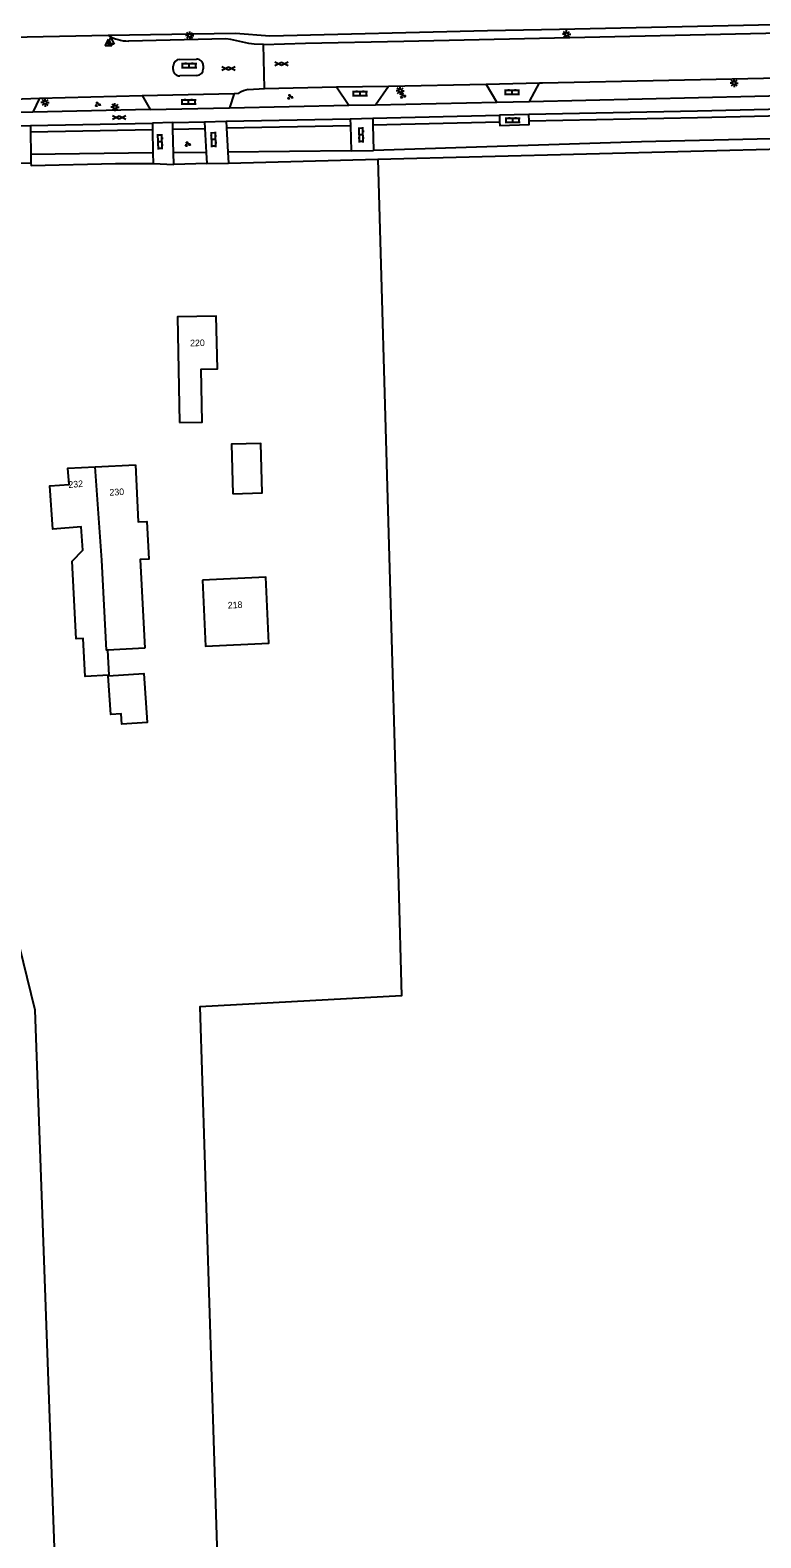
# Model space of a CAD drawing. Extents: x 128999 to 131010, y 395498 to 399007.
# Drawn here: x 130522.1 to 130633, y 395907.2 to 396136.1 of the extents above; entities that cross this region are included whole.
import ezdxf

# ---------------------------------------------------------------- set-up
doc = ezdxf.new("R2010")
doc.units = 0
for name, color, linetype in [('gg-afsc-hekwerk', 7, 'Continuous'), ('gg-anno-huisnummerreeks BGT', 7, 'Continuous'), ('gg-bbg-bijgebouw', 7, 'Continuous'), ('gg-bbg-gedigitaliseerde bebouwing', 7, 'Continuous'), ('gg-bbg-gedigitaliseerde bijgebouw', 7, 'Continuous'), ('gg-bbg-hoofdgebouw', 7, 'Continuous'), ('gg-bbg-tussenscheiding', 7, 'Continuous'), ('gg-knt-verharding', 7, 'Continuous'), ('gt-grn-groengrens', 7, 'Continuous'), ('gt-grn-groengrens NZ', 7, 'Continuous'), ('gt-grn-weggrens', 7, 'Continuous'), ('gt-symb-gesloten verharding', 7, 'Continuous'), ('gt-symb-groenvak', 7, 'Continuous'), ('gt-symb-klinker verharding', 7, 'Continuous'), ('gt-symb-lichtmast', 7, 'Continuous'), ('gt-symb-waterafsluiter', 7, 'Continuous')]:
    doc.layers.add(name, color=color, linetype=linetype)

# ---------------------------------------------------------------- blocks, each defined once
blk = doc.blocks.new('gt0-KL1')
at = {"layer": 'gt-symb-klinker verharding'}
for p, q in [((-1.15, 0.3), (1.15, 0.3)), ((-1, -0.3), (-1, 0.3)), ((-0.5, 0.3), (-0.5, 0.45)), ((0, -0.3), (0, 0.3)), ((0.5, 0.3), (0.5, 0.45)), ((1, -0.3), (1, 0.3)), ((-1.15, -0.3), (1.15, -0.3)), ((-0.5, -0.45), (-0.5, -0.3)), ((0.5, -0.45), (0.5, -0.3))]:
    blk.add_line(p, q, dxfattribs=at)
blk = doc.blocks.new('gt0-GESVH1')
at = {"layer": 'gt-symb-gesloten verharding'}
for p, q in [((-0.99, -0.26), (0.01, 0.24)), ((0.01, -0.26), (-0.99, 0.24)), ((0.01, 0.24), (1.01, -0.26)), ((1.01, 0.24), (0.01, -0.26))]:
    blk.add_line(p, q, dxfattribs=at)
blk = doc.blocks.new('gt0-LMAST')
at = {"layer": 'gt-symb-lichtmast'}
for p, q in [((-0.18, 0.17), (-0.45, 0.44)), ((-0.01, 0.25), (-0.01, 0.62)), ((0.17, 0.17), (0.44, 0.44)), ((-0.26, 0), (-0.63, 0)), ((-0.18, -0.18), (-0.45, -0.45)), ((-0.01, -0.25), (-0.01, -0.63)), ((0.44, -0.45), (0.17, -0.18)), ((0.24, 0), (0.62, 0))]:
    blk.add_line(p, q, dxfattribs=at)
blk.add_circle((-0.01, 0), 0.25, dxfattribs=at)
blk = doc.blocks.new('gt0-GRVAK')
at = {"layer": 'gt-symb-groenvak'}
for p, q in [((-0.11, 0.19), (-0.23, 0.24)), ((-0.18, 0.15), (0.09, 0.15)), ((-0.09, 0.21), (-0.16, 0.32)), ((-0.05, 0.21), (-0.05, 0.39)), ((0, 0.21), (0.06, 0.32)), ((0.01, 0.19), (0.13, 0.24)), ((0.26, -0.05), (0.2, 0.06)), ((0.31, -0.05), (0.31, 0.13)), ((0.35, -0.05), (0.41, 0.06)), ((-0.24, -0.23), (-0.36, -0.18)), ((-0.32, -0.26), (-0.05, -0.26)), ((-0.23, -0.21), (-0.29, -0.1)), ((-0.18, -0.2), (-0.18, -0.02)), ((-0.14, -0.21), (-0.07, -0.1)), ((-0.12, -0.23), (0, -0.18)), ((0.24, -0.07), (0.12, -0.02)), ((0.17, -0.11), (0.44, -0.11)), ((0.37, -0.07), (0.49, -0.02))]:
    blk.add_line(p, q, dxfattribs=at)
blk = doc.blocks.new('gt0-WAFSL')
at = {"layer": 'gt-symb-waterafsluiter'}
for p, q in [((-0.5, -0.33), (0, 0.67)), ((0, 0.67), (0.5, -0.33)), ((0.5, -0.33), (-0.5, -0.33))]:
    blk.add_line(p, q, dxfattribs=at)

msp = doc.modelspace()

# ---------------------------------------------------------------- linework, layer by layer
at = {"layer": 'gg-afsc-hekwerk'}
msp.add_line((130548.91, 396115.83), (130543.9, 396115.68), dxfattribs=at)
at = {"layer": 'gg-bbg-bijgebouw'}
msp.add_lwpolyline([(130552.84, 396065.7), (130557.31, 396065.82), (130557.11, 396073.33), (130552.64, 396073.21), (130552.84, 396065.7)], dxfattribs=at)
at = {"layer": 'gg-bbg-gedigitaliseerde bebouwing'}
msp.add_lwpolyline([(130548.26, 396052.59), (130548.73, 396042.58), (130558.34, 396043.04), (130557.86, 396053.05), (130548.26, 396052.59)], dxfattribs=at)
at = {"layer": 'gg-bbg-gedigitaliseerde bijgebouw'}
msp.add_lwpolyline([(130533.93, 396038.04), (130539.33, 396038.42), (130539.84, 396030.97), (130536.03, 396030.7), (130535.92, 396032.29), (130534.34, 396032.18), (130533.93, 396038.04)], dxfattribs=at)
at = {"layer": 'gg-bbg-hoofdgebouw'}
for p, q in [((130531.99, 396069.8), (130538.07, 396070.12)), ((130539.52, 396042.28), (130533.83, 396041.98))]:
    msp.add_line(p, q, dxfattribs=at)
for points in [[(130544.77, 396076.51), (130548.19, 396076.58), (130548.04, 396084.62), (130550.51, 396084.67), (130550.35, 396092.67), (130544.46, 396092.56), (130544.77, 396076.51)], [(130533.83, 396041.98), (130534.03, 396038.14), (130530.44, 396037.95), (130530.13, 396043.75), (130529.11, 396043.7), (130528.5, 396055.47), (130530.11, 396057.13), (130529.84, 396060.67), (130525.56, 396060.35), (130525.07, 396066.89), (130528.01, 396067.11), (130527.83, 396069.58), (130531.99, 396069.8)], [(130538.07, 396070.12), (130538.52, 396061.44), (130539.83, 396061.51), (130540.13, 396055.77), (130538.82, 396055.7), (130539.52, 396042.28)]]:
    msp.add_lwpolyline(points, dxfattribs=at)
at = {"layer": 'gg-bbg-tussenscheiding'}
msp.add_lwpolyline([(130533.83, 396041.98), (130533.67, 396041.97), (130532.97, 396055.64), (130531.99, 396069.8)], dxfattribs=at)
at = {"layer": 'gg-knt-verharding'}
for p, q in [((130533.95, 396135.3), (130519.18, 396134.98)), ((130557.5, 396133.91), (130556.11, 396133.95)), ((130557.68, 396127.24), (130557.5, 396133.91)), ((130543.81, 396130.13), (130543.82, 396130.63)), ((130544.78, 396131.66), (130547.36, 396131.7)), ((130548.37, 396130.72), (130548.38, 396130.21)), ((130547.4, 396129.21), (130544.83, 396129.15)), ((130576.5, 396127.61), (130591.3, 396127.88)), ((130591.3, 396127.88), (130591.32, 396127.88)), ((130591.32, 396127.88), (130599.37, 396128.07)), ((130592.92, 396125.16), (130591.32, 396127.88)), ((130597.85, 396125.27), (130599.37, 396128.07)), ((130599.37, 396128.07), (130599.84, 396128.08)), ((130599.84, 396128.08), (130688.07, 396129.97)), ((130516.59, 396125.52), (130523.51, 396125.75)), ((130523.51, 396125.75), (130522.52, 396123.64)), ((130523.51, 396125.75), (130539.08, 396126.16)), ((130539.08, 396126.16), (130553.04, 396126.48)), ((130539.08, 396126.16), (130540.31, 396124.02)), ((130553.04, 396126.48), (130552.35, 396124.3)), ((130553.04, 396126.48), (130553.79, 396126.53)), ((130555.18, 396127.07), (130557.68, 396127.24)), ((130557.68, 396127.24), (130568.6, 396127.47)), ((130568.6, 396127.47), (130576.5, 396127.61)), ((130568.6, 396127.47), (130570.48, 396124.68)), ((130574.49, 396124.75), (130576.5, 396127.61)), ((130522.52, 396123.64), (130518.15, 396123.54)), ((130540.31, 396124.02), (130522.52, 396123.64)), ((130540.31, 396124.02), (130552.35, 396124.3)), ((130552.35, 396124.3), (130570.48, 396124.68)), ((130570.48, 396124.68), (130574.49, 396124.75)), ((130574.49, 396124.75), (130592.92, 396125.16)), ((130592.92, 396125.16), (130597.85, 396125.27)), ((130597.79, 396123.27), (130593.3, 396123.16)), ((130597.82, 396122.27), (130597.79, 396123.27)), ((130518.59, 396121.55), (130522.14, 396121.63)), ((130522.14, 396121.63), (130540.66, 396121.99)), ((130522.14, 396121.63), (130522.15, 396120.63)), ((130543.75, 396122.05), (130540.66, 396121.99)), ((130540.66, 396121.99), (130540.68, 396120.99)), ((130540.68, 396120.99), (130540.74, 396117.44)), ((130543.75, 396122.05), (130548.54, 396122.18)), ((130543.77, 396121.05), (130543.75, 396122.05)), ((130543.77, 396121.05), (130548.6, 396121.18)), ((130543.86, 396117.47), (130543.77, 396121.05)), ((130548.54, 396122.18), (130551.87, 396122.27)), ((130548.54, 396122.18), (130548.6, 396121.18)), ((130548.6, 396121.18), (130548.81, 396117.53)), ((130551.87, 396122.27), (130570.68, 396122.63)), ((130551.87, 396122.27), (130551.92, 396121.27)), ((130551.92, 396121.27), (130552.12, 396117.57)), ((130570.68, 396122.63), (130574.09, 396122.73)), ((130570.68, 396122.63), (130570.71, 396121.63)), ((130570.71, 396121.63), (130570.81, 396117.75)), ((130574.09, 396122.73), (130593.3, 396123.16)), ((130574.09, 396122.73), (130574.11, 396121.73)), ((130574.11, 396121.73), (130574.22, 396117.8)), ((130593.3, 396123.16), (130593.33, 396122.16)), ((130522.15, 396120.63), (130522.21, 396117.23)), ((130522.21, 396117.23), (130522.23, 396115.88)), ((130540.74, 396117.44), (130540.77, 396115.86)), ((130543.9, 396115.68), (130543.86, 396117.47)), ((130548.81, 396117.53), (130548.91, 396115.83)), ((130552.12, 396117.57), (130552.21, 396115.89)), ((130522.23, 396115.88), (130518.96, 396115.78))]:
    msp.add_line(p, q, dxfattribs=at)
for points in [[(130779.08, 396140.06), (130602.43, 396136.21), (130591.5, 396136)], [(130557.5, 396133.91), (130563.91, 396134.13), (130578.82, 396134.43), (130777.82, 396138.84)], [(130591.5, 396136), (130558.49, 396135.2), (130553.25, 396135.59), (130533.95, 396135.3)], [(130556.11, 396133.95), (130555.3, 396134.04), (130552.57, 396134.65), (130551.81, 396134.77), (130537.05, 396134.43)], [(130597.85, 396125.27), (130649.18, 396126.45), (130656.22, 396126.63), (130663.5, 396127.01), (130670.92, 396127.54), (130682.3, 396128.28), (130686.74, 396128.49), (130690.65, 396128.56)], [(130691.26, 396126.57), (130686.91, 396126.43), (130682.58, 396126.23), (130671.33, 396125.5), (130663.58, 396124.95), (130656.49, 396124.59), (130649.22, 396124.39), (130623.35, 396123.79), (130597.79, 396123.27)], [(130593.33, 396122.16), (130593.35, 396121.62), (130597.83, 396121.75), (130597.82, 396122.27)]]:
    msp.add_lwpolyline(points, dxfattribs=at)
for centre, radius, start, end in [((130537.01, 396140.27), 5.83, 238.3369, 270.4457), ((130544.83, 396130.65), 1.01, 92.5004, 180.7794), ((130544.79, 396130.12), 0.979, 179.4419, 272.328), ((130547.38, 396130.71), 0.994, 0.6008, 91.1214), ((130547.38, 396130.21), 0.997, 271.0386, 0.0627), ((130555.89, 396123.17), 3.97, 100.2679, 121.9669)]:
    msp.add_arc(centre, radius, start, end, dxfattribs=at)
at = {"layer": 'gt-grn-groengrens'}
for p, q in [((130574.84, 396116.49), (130690.6, 396119.51)), ((130540.74, 396117.44), (130522.21, 396117.23)), ((130548.81, 396117.53), (130543.86, 396117.47)), ((130570.81, 396117.75), (130552.12, 396117.57)), ((130552.21, 396115.89), (130574.84, 396116.49))]:
    msp.add_line(p, q, dxfattribs=at)
for points in [[(130691.72, 396120.93), (130656.6, 396120.09), (130614.87, 396119.12), (130574.22, 396117.8)], [(130574.84, 396116.49), (130577.98, 396006.36), (130578.46, 395989.5), (130547.84, 395987.81), (130552.09, 395852.97), (130527.73, 395852.24), (130522.86, 395987.31), (130519.88, 395999.52), (130514.76, 396007.01), (130516.32, 396021.25), (130497.85, 396023.27)], [(130522.23, 396115.88), (130522.24, 396115.54), (130535.06, 396115.84), (130540.77, 396115.86)]]:
    msp.add_lwpolyline(points, dxfattribs=at)
at = {"layer": 'gt-grn-groengrens NZ'}
for p, q in [((130522.15, 396120.63), (130540.68, 396120.99)), ((130551.92, 396121.27), (130570.71, 396121.63)), ((130574.11, 396121.73), (130593.33, 396122.16))]:
    msp.add_line(p, q, dxfattribs=at)
msp.add_lwpolyline([(130691.48, 396125.58), (130686.94, 396125.43), (130682.64, 396125.23), (130671.4, 396124.5), (130663.64, 396123.96), (130656.53, 396123.59), (130649.25, 396123.39), (130623.37, 396122.79), (130597.82, 396122.27)], dxfattribs=at)
at = {"layer": 'gt-grn-weggrens'}
for p, q in [((130570.81, 396117.75), (130574.22, 396117.8)), ((130540.77, 396115.86), (130543.9, 396115.68)), ((130548.91, 396115.83), (130552.21, 396115.89))]:
    msp.add_line(p, q, dxfattribs=at)

# ---------------------------------------------------------------- block references
at = {"layer": 'gt-symb-gesloten verharding'}
for p in [(130552.2, 396130.28), (130560.24, 396130.98), (130535.61, 396122.85)]:
    msp.add_blockref('gt0-GESVH1', p, dxfattribs=at)
at = {"layer": 'gt-symb-groenvak'}
for p in [(130561.53, 396125.96), (130578.64, 396126.14), (130532.33, 396124.84), (130545.98, 396118.79)]:
    msp.add_blockref('gt0-GRVAK', p, dxfattribs=at)
at = {"layer": 'gt-symb-klinker verharding'}
for p in [(130546.24, 396130.72), (130546.15, 396125.19), (130572.16, 396126.48), (130595.23, 396126.66), (130595.32, 396122.42)]:
    msp.add_blockref('gt0-KL1', p, dxfattribs=at)
at = {"layer": 'gt-symb-klinker verharding', "rotation": 91.317570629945}
for p in [(130572.33, 396120.18), (130541.83, 396119.14), (130549.95, 396119.48)]:
    msp.add_blockref('gt0-KL1', p, dxfattribs=at)
at = {"layer": 'gt-symb-lichtmast'}
for p in [(130546.32, 396135.29), (130603.5, 396135.46), (130628.93, 396128.06), (130524.38, 396125.1), (130578.26, 396126.89), (130534.98, 396124.4)]:
    msp.add_blockref('gt0-LMAST', p, dxfattribs=at)
at = {"layer": 'gt-symb-waterafsluiter'}
for p in [(130534.34, 396134.27), (130534.01, 396134.03)]:
    msp.add_blockref('gt0-WAFSL', p, dxfattribs=at)

# ---------------------------------------------------------------- texts
at = {"layer": 'gg-anno-huisnummerreeks BGT'}
for s, rotation, p in [('220', 1.1, (130546.38, 396088.09)), ('232', 4.2, (130527.94, 396066.58)), ('230', 3, (130534.16, 396065.41)), ('218', 2.8, (130552.11, 396048.27))]:
    msp.add_text(s, height=1, rotation=rotation, dxfattribs=at).set_placement(p)

doc.saveas('drawing.dxf')
